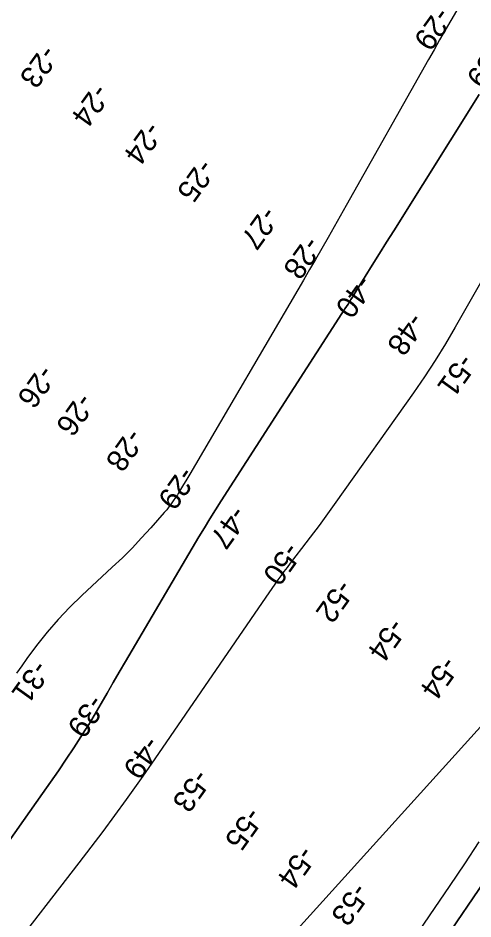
# Model space of a CAD drawing. Extents: x 3879599 to 3900814, y 146526 to 168888.
# Drawn here: x 3891140 to 3891843, y 154874 to 156266 of the extents above; entities that cross this region are included whole.
import ezdxf

# ---------------------------------------------------------------- set-up
doc = ezdxf.new("R2010")
doc.units = 0
for name, color, linetype in [('V-RIVR-RANG', 7, 'Continuous'), ('V-TOPO-DPTH', 7, 'Continuous'), ('V-TOPO-MAJR', 7, 'Continuous'), ('V-TOPO-MINR', 7, 'Continuous')]:
    doc.layers.add(name, color=color, linetype=linetype)

msp = doc.modelspace()

# ---------------------------------------------------------------- linework, layer by layer
at = {"layer": 'V-RIVR-RANG'}
msp.add_lwpolyline([(3887950.4, 150855.4), (3895383.9, 159071.9)], dxfattribs=at)
at = {"layer": 'V-TOPO-DPTH'}
for points in [[(3891817.9, 156276.6), (3891809.2, 156261.7), (3891800.5, 156246.8), (3891791.9, 156231.8), (3891783.3, 156216.8), (3891774.8, 156201.8), (3891647.7, 155976.2), (3891638.4, 155959.6), (3891629, 155943.1), (3891619.5, 155926.6), (3891610.1, 155910), (3891600.3, 155893), (3891595.6, 155885), (3891591, 155877.1), (3891586.4, 155869.1), (3891581.7, 155861.1), (3891405.9, 155561.4), (3891402.8, 155556.1), (3891399.6, 155550.7), (3891396.4, 155545.4), (3891393.2, 155540.1), (3891389.4, 155533.7), (3891388.1, 155531.6), (3891386.7, 155529.5), (3891385.4, 155527.4), (3891384, 155525.3), (3891380.4, 155520), (3891377.1, 155515.3), (3891373.7, 155510.7), (3891370.2, 155506.3), (3891366.5, 155502), (3891345.8, 155478.5), (3891331.5, 155462.7), (3891316.8, 155447.2), (3891301.7, 155432.2), (3891286.2, 155417.5), (3891239.1, 155374.1), (3891220.3, 155355.9), (3891202.3, 155337), (3891185.3, 155317.1), (3891169.1, 155296.5), (3891154.2, 155276.5), (3891146.2, 155265.3), (3891138.4, 155254)], [(3891817.9, 156276.6), (3891809.2, 156261.7), (3891800.5, 156246.8), (3891791.9, 156231.8), (3891783.3, 156216.8), (3891774.8, 156201.8), (3891647.7, 155976.2), (3891638.4, 155959.6), (3891629, 155943.1), (3891619.5, 155926.6), (3891610.1, 155910), (3891600.3, 155893), (3891595.6, 155885), (3891591, 155877.1), (3891586.4, 155869.1), (3891581.7, 155861.1), (3891405.9, 155561.4), (3891402.8, 155556.1), (3891399.6, 155550.7), (3891396.4, 155545.4), (3891393.2, 155540.1), (3891389.4, 155533.7), (3891388.1, 155531.6), (3891386.7, 155529.5), (3891385.4, 155527.4), (3891384, 155525.3), (3891380.4, 155520), (3891377.1, 155515.3), (3891373.7, 155510.7), (3891370.2, 155506.3), (3891366.5, 155502), (3891345.8, 155478.5), (3891331.5, 155462.7), (3891316.8, 155447.2), (3891301.7, 155432.2), (3891286.2, 155417.5), (3891239.1, 155374.1), (3891220.3, 155355.9), (3891202.3, 155337), (3891185.3, 155317.1), (3891169.1, 155296.5), (3891154.2, 155276.5), (3891146.2, 155265.3), (3891138.4, 155254)], [(3891043.3, 154877.3), (3891178.5, 155068.3), (3891190.8, 155085.8), (3891202.9, 155103.3), (3891214.8, 155121), (3891226.6, 155138.8), (3891244.9, 155166.7), (3891247.4, 155170.6), (3891249.9, 155174.6), (3891252.3, 155178.5), (3891254.6, 155182.5), (3891268.7, 155206.9), (3891278, 155223.2), (3891287.4, 155239.4), (3891296.8, 155255.5), (3891306.3, 155271.7), (3891420, 155464.2), (3891428.4, 155478.4), (3891437, 155492.5), (3891445.7, 155506.4), (3891454.6, 155520.3), (3891641, 155809.3), (3891643.3, 155812.9), (3891645.6, 155816.5), (3891647.9, 155820.1), (3891650.3, 155823.7), (3891652.6, 155827.3), (3891654.9, 155831), (3891657.1, 155834.6), (3891659.4, 155838.2), (3891676.8, 155866.4), (3891687.8, 155884.1), (3891698.8, 155901.8), (3891709.9, 155919.4), (3891720.9, 155937.1), (3891853.1, 156147.6)], [(3891043.3, 154877.3), (3891178.5, 155068.3), (3891190.8, 155085.8), (3891202.9, 155103.3), (3891214.8, 155121), (3891226.6, 155138.8), (3891244.9, 155166.7), (3891247.4, 155170.6), (3891249.9, 155174.6), (3891252.3, 155178.5), (3891254.6, 155182.5), (3891268.7, 155206.9), (3891278, 155223.2), (3891287.4, 155239.4), (3891296.8, 155255.5), (3891306.3, 155271.7), (3891420, 155464.2), (3891428.4, 155478.4), (3891437, 155492.5), (3891445.7, 155506.4), (3891454.6, 155520.3), (3891641, 155809.3), (3891643.3, 155812.9), (3891645.6, 155816.5), (3891647.9, 155820.1), (3891650.3, 155823.7), (3891652.6, 155827.3), (3891654.9, 155831), (3891657.1, 155834.6), (3891659.4, 155838.2), (3891676.8, 155866.4), (3891687.8, 155884.1), (3891698.8, 155901.8), (3891709.9, 155919.4), (3891720.9, 155937.1), (3891853.1, 156147.6)], [(3891801.8, 154845.7), (3891859.9, 154931.1)], [(3891859.9, 154931.1), (3891801.8, 154845.7)]]:
    msp.add_lwpolyline(points, dxfattribs=at)
at = {"layer": 'V-TOPO-MAJR'}
for points in [[(3891865.1, 155874.5), (3891816, 155788.4), (3891800.7, 155762.5), (3891784.9, 155736.9), (3891768.4, 155711.8), (3891751.4, 155687.1), (3891631.7, 155518.2), (3891618.7, 155500), (3891605.5, 155482), (3891592.1, 155464.1), (3891578.5, 155446.3), (3891561, 155423.6), (3891556.2, 155417.2), (3891551.3, 155410.8), (3891546.6, 155404.3), (3891541.9, 155397.8), (3891537.2, 155391.2), (3891532.6, 155384.6), (3891528, 155378), (3891523.4, 155371.4), (3891352, 155121.4), (3891347.4, 155114.8), (3891342.8, 155108.1), (3891338.2, 155101.5), (3891333.5, 155095), (3891307.4, 155058.6), (3891289.5, 155033.9), (3891271.5, 155009.4), (3891253.2, 154985.1), (3891234.7, 154960.9), (3891123.9, 154817.7)], [(3891744.4, 154832.3), (3891808.1, 154926.1), (3891830.7, 154959.7), (3891853.2, 154993.4)]]:
    msp.add_lwpolyline(points, dxfattribs=at)
at = {"layer": 'V-TOPO-MINR'}
for points in [[(3891817.9, 156276.6), (3891809.2, 156261.7), (3891800.5, 156246.8), (3891791.9, 156231.8), (3891783.3, 156216.8), (3891774.8, 156201.8), (3891647.7, 155976.2), (3891638.4, 155959.6), (3891629, 155943.1), (3891619.5, 155926.6), (3891610.1, 155910), (3891600.3, 155893), (3891595.6, 155885), (3891591, 155877.1), (3891586.4, 155869.1), (3891581.7, 155861.1), (3891405.9, 155561.4), (3891402.8, 155556.1), (3891399.6, 155550.7), (3891396.4, 155545.4), (3891393.2, 155540.1), (3891389.4, 155533.7), (3891388.1, 155531.6), (3891386.7, 155529.5), (3891385.4, 155527.4), (3891384, 155525.3), (3891380.4, 155520), (3891377.1, 155515.3), (3891373.7, 155510.7), (3891370.2, 155506.3), (3891366.5, 155502), (3891345.8, 155478.5), (3891331.5, 155462.7), (3891316.8, 155447.2), (3891301.7, 155432.2), (3891286.2, 155417.5), (3891239.1, 155374.1), (3891220.3, 155355.9), (3891202.3, 155337), (3891185.3, 155317.1), (3891169.1, 155296.5), (3891154.2, 155276.5), (3891146.2, 155265.3), (3891138.4, 155254)], [(3891853.1, 156147.6), (3891720.9, 155937.1), (3891709.9, 155919.4), (3891698.8, 155901.8), (3891687.8, 155884.1), (3891676.8, 155866.4), (3891659.4, 155838.2), (3891657.1, 155834.6), (3891654.9, 155831), (3891652.6, 155827.3), (3891650.3, 155823.7), (3891647.9, 155820.1), (3891645.6, 155816.5), (3891643.3, 155812.9), (3891641, 155809.3), (3891454.6, 155520.3), (3891445.7, 155506.4), (3891437, 155492.5), (3891428.4, 155478.4), (3891420, 155464.2), (3891306.3, 155271.7), (3891296.8, 155255.5), (3891287.4, 155239.4), (3891278, 155223.2), (3891268.7, 155206.9), (3891254.6, 155182.5), (3891252.3, 155178.5), (3891249.9, 155174.6), (3891247.4, 155170.6), (3891244.9, 155166.7), (3891226.6, 155138.8), (3891214.8, 155121), (3891202.9, 155103.3), (3891190.8, 155085.8), (3891178.5, 155068.3), (3891043.3, 154877.3)], [(3891801.8, 154845.7), (3891859.9, 154931.1)]]:
    msp.add_lwpolyline(points, dxfattribs=at)

# ---------------------------------------------------------------- texts
at = {"layer": 'V-RIVR-RANG'}
for s, rotation, p in [('-29', 234.3277, (3891788.2, 156284.5)), ('-23', 234.0683, (3891179.4, 156226.2)), ('-39', 234.3277, (3891869.4, 156226.1)), ('-24', 234.0683, (3891259.5, 156166.4)), ('-24', 234.0683, (3891340.6, 156107.9)), ('-25', 234.0683, (3891422.3, 156050.1)), ('-27', 234.2084, (3891520.2, 155977.1)), ('-28', 234.2084, (3891586.5, 155930.9)), ('-40', 234.2084, (3891666.9, 155871.1)), ('-48', 234.2084, (3891746.9, 155813.1)), ('-51', 234.2084, (3891824.5, 155749.4)), ('-26', 234.4529, (3891175.6, 155732)), ('-26', 234.4529, (3891235.3, 155688.9)), ('-28', 234.4529, (3891311.9, 155634)), ('-29', 234.4529, (3891392.7, 155575.2)), ('-47', 234.4529, (3891472.4, 155514.7)), ('-50', 234.4529, (3891554.8, 155458.3)), ('-52', 234.4529, (3891636.5, 155400.5)), ('-54', 234.4529, (3891716.8, 155340.8)), ('-54', 234.4529, (3891797.9, 155282.3)), ('-31', 234.4529, (3891166.5, 155276.1)), ('-39', 234.4529, (3891252.6, 155222.9)), ('-49', 234.4529, (3891338.8, 155159)), ('-53', 234.4529, (3891415, 155107.9)), ('-55', 234.4529, (3891495.8, 155049.1)), ('-54', 234.4529, (3891577.3, 154989.7)), ('-53', 234.4529, (3891660.3, 154932.5))]:
    msp.add_text(s, height=33.5, rotation=rotation, dxfattribs=at).set_placement(p)

doc.saveas('drawing.dxf')
